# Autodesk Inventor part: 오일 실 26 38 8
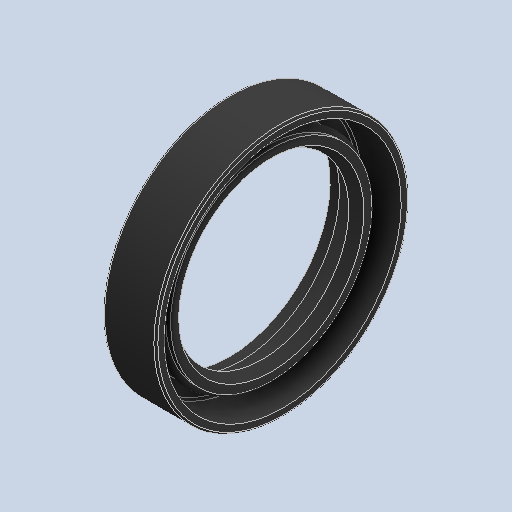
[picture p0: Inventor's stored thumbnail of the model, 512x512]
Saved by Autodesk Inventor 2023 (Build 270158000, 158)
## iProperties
Created: 2025-03
Part Number: 오일 실 26 38 8
Material: 고무
Description: 오일-실
Document SubType Name: Modeling
Designer: ADMIN_PC
Density: 0.93 g/cm^3
Appearance: 기본값
Author: jhkim
Sending System: Autodesk Inventor 2025
Preprocessor: ST-DEVELOPER v20
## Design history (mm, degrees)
feature "Solid1"
node "솔리드1"
